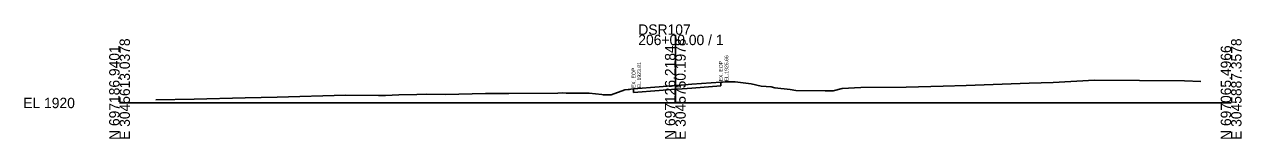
# Model space of a CAD drawing. Extents: x -26 to 19003, y -31 to 24541.
# Drawn here: x 1974.3 to 2302.8, y 7490.3 to 7521.3 of the extents above; entities that cross this region are included whole.
import ezdxf

# ---------------------------------------------------------------- set-up
doc = ezdxf.new("R2010")
doc.units = 0
for name, color, linetype in [('DESIGN - SHEET - Light Grid', 7, 'Continuous'), ('SURVEY - GROUND - Existing Pavement Layer', 7, 'Continuous'), ('SURVEY - GROUND - Existing Pavement Text', 7, 'Continuous'), ('SURVEY - GROUND - Top of Ground', 7, 'Continuous')]:
    doc.layers.add(name, color=color, linetype=linetype)

msp = doc.modelspace()

# ---------------------------------------------------------------- linework, layer by layer
at = {"layer": 'DESIGN - SHEET - Light Grid'}
for p, q in [((2150, 7500), (2150, 7518.48)), ((2000, 7500), (2150, 7500)), ((2150, 7500), (2300, 7500))]:
    msp.add_line(p, q, dxfattribs=at)
at = {"layer": 'SURVEY - GROUND - Existing Pavement Layer'}
for p, q in [((2138.74, 7502.81), (2138.74, 7503.81)), ((2145.62, 7503.34), (2150, 7503.7)), ((2150, 7503.7), (2150.56, 7503.75)), ((2150.56, 7503.75), (2154.44, 7504.05)), ((2154.44, 7504.05), (2162.29, 7504.66)), ((2162.29, 7505.66), (2162.29, 7504.66)), ((2138.74, 7502.81), (2145.62, 7503.34))]:
    msp.add_line(p, q, dxfattribs=at)
at = {"layer": 'SURVEY - GROUND - Top of Ground'}
msp.add_lwpolyline([(2009.82, 7500.83), (2020.14, 7501.04), (2033.89, 7501.37), (2042.57, 7501.6), (2060.96, 7502.08), (2069.89, 7502.01), (2071.26, 7502.02), (2071.81, 7502.02), (2075.34, 7502.21), (2080.21, 7502.33), (2082.77, 7502.34), (2088.01, 7502.29), (2098.73, 7502.52), (2101.14, 7502.55), (2105.02, 7502.55), (2118.31, 7502.68), (2119.45, 7502.71), (2120.5, 7502.69), (2126.72, 7502.69), (2130.2, 7502.28), (2130.56, 7502.23), (2132.65, 7502.24), (2136.33, 7503.55), (2137.26, 7503.65), (2137.64, 7503.68), (2137.98, 7503.72), (2138.74, 7503.81), (2145.62, 7504.34), (2150, 7504.7), (2150.56, 7504.75), (2154.44, 7505.05), (2162.29, 7505.66), (2162.69, 7505.68), (2163.49, 7505.73), (2164.43, 7505.72), (2166.11, 7505.69), (2170.48, 7505.15), (2173.13, 7504.58), (2175.85, 7504.33), (2176.81, 7504.1), (2180.97, 7503.68), (2182.52, 7503.35), (2190.46, 7503.26), (2192.56, 7503.28), (2195.03, 7503.92), (2200.09, 7504.19), (2212.32, 7504.29), (2222.31, 7504.59), (2228.47, 7504.71), (2245.53, 7505.33), (2252.01, 7505.51), (2263.15, 7506.16), (2287.4, 7505.99), (2291.85, 7505.85)], dxfattribs=at)

# ---------------------------------------------------------------- texts
at = {"layer": 'DESIGN - SHEET - Light Grid'}
for s, p in [('DSR107', (2140, 7518.48)), ('206+00.00 / 1', (2140, 7515.68)), ('EL 1920', (1974, 7498.6))]:
    msp.add_text(s, height=2.8, dxfattribs=at).set_placement(p)
for s, p in [('E 3045613.0378', (2002.8, 7490)), ('E 3045750.1978', (2152.8, 7490)), ('E 3045887.3578', (2302.8, 7490)), ('N 697186.9401', (2000, 7490)), ('N 697126.2184', (2150, 7490)), ('N 697065.4966', (2300, 7490))]:
    msp.add_text(s, height=2.8, rotation=90, dxfattribs=at).set_placement(p)
at = {"layer": 'SURVEY - GROUND - Existing Pavement Text'}
for s, p in [('EL.1923.81', (2140.74, 7504.01)), ('EX. EOP', (2162.79, 7505.86)), ('EL.1925.66', (2164.29, 7505.86)), ('EX. EOP', (2139.24, 7504.01))]:
    msp.add_text(s, height=1, rotation=90, dxfattribs=at).set_placement(p)

doc.saveas('drawing.dxf')
